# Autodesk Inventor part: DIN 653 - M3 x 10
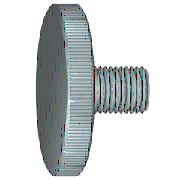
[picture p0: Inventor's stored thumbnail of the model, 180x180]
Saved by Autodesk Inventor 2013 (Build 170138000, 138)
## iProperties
Created: 2012-02
Part Number: DIN 653 - M3 x 10
Material: Stahl, weich
Description: Rändelschraube
Document SubType Name: Modeling
Standard: DIN 653
Designer: rYan
Standards Organization: DIN
Language: de-DE
Size Designation: M3 x 10
Categories: <MemberInstance><Categories><Category DisplayName="Verbindungselemente" InternalName="e4da775c-781d-43d5-af7c-5136215cf5a6" Mnemonic="FSTN"><Category DisplayNam
Density: 1 g/cm^3
IsCustomPart: 0
Author: rYan
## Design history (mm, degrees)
revolve "Körper" stored, may be unused: angle "d8" = 90 deg
node "IDS_WORKPLANE{1}"
workplane "Work Plane2"
body "Solid1"
feature "Gewinde" dims "d2" = 8.224 (= GEL - 0.092 x GD), "d3" = 0
chamfer "Fase1" distance "d10" = 0.3 (= PHH); stored, may be unused: angle "d11" = 45 deg (= FAWI), second distance "d38" = 0.3 (= PHH)
sketch "Skizze1"
  geometry: L1 (-2.5, 0)-(10, 0); L2 (10, 0)-(10, 5); L3 (9.673, 1.5)-(0, 1.5); L4 (0, -1.2)-(0, 7.2) reference; L5 (0, 1.5)-(0, 6); L6 (0, 6)-(-2.5, 6); L7 (-2.5, 6)-(-2.5, 0); L8 (-5.016, 0)-(12.597, 0) reference; A1 r 3.6 centre (6.4, 0) between (10, 0) and (9.673, 1.5)
  constraints: 13 end point, 2 perpendicular, 2 point on circle, 2 vertical alignment, 1 centre point, 1 collinear, 1 parallel, 1 point on line, 1 tangent
  dimensions: "d1" = 3 diameter of L3 L1 (= GD); "d6" = 12 diameter of L6 L1 (= KOD); "d7" = 2.5 distance between parallel lines of L5 L7 (= KOH); "d9" = 3.6 radius of A1 (= 1.2 x GD); "d41" = 10 distance between parallel lines of L2 L5 (= NLG)
other parameters: "GD" = 3 [user parameter; used in 3 equation terms], "NLG" = 10 [user parameter; used in 1 equation term], "GEL" = 8.5 [user parameter; used in 1 equation term], "KOD" = 12 [user parameter; used in 1 equation term], "KOH" = 2.5 [user parameter; used in 2 equation terms], "GAL" = 0.30673 (= 0.61345 x PTC) [user parameter], "d4" = 0, "SD" = 0 [user parameter], "LADI" = 3 (= NND) [user parameter], "PHH" = 0.3 [user parameter; used in 2 equation terms], "FAWI" = 45 deg [user parameter; used in 1 equation term], "d12" = -1.25 (= -0.5 x KOH), "T" = 0.5 [user parameter], "d39" = 0, "d42" = 0, "NND" = 3 [user parameter; used in 1 equation term], "PTC" = 0.5 [user parameter; used in 2 equation terms]
